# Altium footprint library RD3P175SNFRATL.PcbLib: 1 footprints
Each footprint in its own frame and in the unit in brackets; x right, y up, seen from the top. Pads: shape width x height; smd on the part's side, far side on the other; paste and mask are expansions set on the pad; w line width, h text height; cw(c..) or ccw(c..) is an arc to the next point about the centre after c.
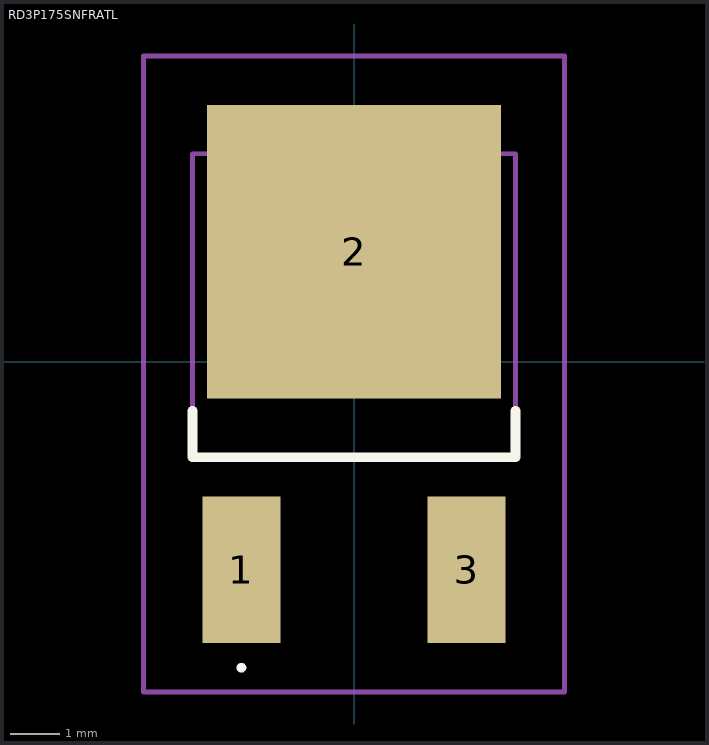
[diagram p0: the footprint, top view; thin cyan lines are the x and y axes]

## RD3P175SNFRATL [mm]
pads (3):
  rect 1.6x3 smd: 1(-2.3,-4.25) 3(2.3,-4.25)
  rect 6x6 smd: 2(0,2.25)
Top Overlay:
  lines w0.1: -2.3,-6.3 cw(c-2.3,-6.25) -2.3,-6.2 ; -2.3,-6.3 -2.3,-6.3 ; -2.3,-6.3 ccw(c-2.3,-6.25) -2.3,-6.2 ; -2.3,-6.2 -2.3,-6.2
  lines w0.2: -3.3,-1 -3.3,-1.95 3.3,-1.95 3.3,-1
Mechanical 15:
  lines w0.1: -3.3,-1.95 3.3,-1.95 3.3,4.25 -3.3,4.25 -3.3,-1.95
Mechanical 20:
  lines w0.1: -4.3,-6.75 4.3,-6.75 4.3,6.25 -4.3,6.25 -4.3,-6.75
